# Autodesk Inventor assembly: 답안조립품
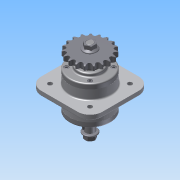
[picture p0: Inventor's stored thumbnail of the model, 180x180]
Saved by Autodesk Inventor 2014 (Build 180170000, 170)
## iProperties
Created: 2015-09
Part Number: 답안조립품
Document SubType Name: Assembly
Designer: study
Author: study
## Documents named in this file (12)
- C:\Users\study\Desktop\450909V1012\답안조립품.iam
- C:\Users\study\Desktop\450909V1012\1-본체.ipt
- C:\Users\study\Desktop\450909V1012\6-베어링 6206.ipt
- C:\Users\study\Desktop\450909V1012\3-축.ipt
- C:\Users\study\Desktop\450909V1012\2-커버.ipt
- C:\Users\study\Desktop\450909V1012\4-V벨트풀리.ipt
- C:\Users\study\Desktop\450909V1012\11-키 6x6.ipt
- C:\Users\study\Desktop\450909V1012\5-체인 스프로킷.ipt
- C:\Users\study\Desktop\450909V1012\8-오일실 30x42.ipt
- C:\Users\study\Desktop\450909V1012\9-M16-너트.ipt
- C:\Users\study\Desktop\450909V1012\10-M6.ipt
- C:\Users\study\Desktop\450909V1012\7-부시.ipt
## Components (23 placed, 11 different names)
1. 1-본체:1
2. 6-베어링 6206:1
3. 6-베어링 6206:2
4. 3-축:1 — 각도:1, 각도:2
5. 2-커버:1
6. 2-커버:2
7. 4-V벨트풀리:1
8. 11-키 6x6:1 — 각도:1
9. 11-키 6x6:2 — 각도:2
10. 5-체인 스프로킷:1
11. 8-8-오일실 30x42:1
12. 9-M16 너트:1
13. 9-M16 너트:2
14. 7-부시:1
15. 8-8-오일실 30x42:2
16. 10-M6:1
17. 10-M6:2
18. 10-M6:3
19. 10-M6:4
20. 10-M6:5
21. 10-M6:6
22. 10-M6:7
23. 10-M6:8
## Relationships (2: Angle 2)
- 각도:1 [Angle]: 3-축:1 ↔ 11-키 6x6:1
- 각도:2 [Angle]: 3-축:1 ↔ 11-키 6x6:2
